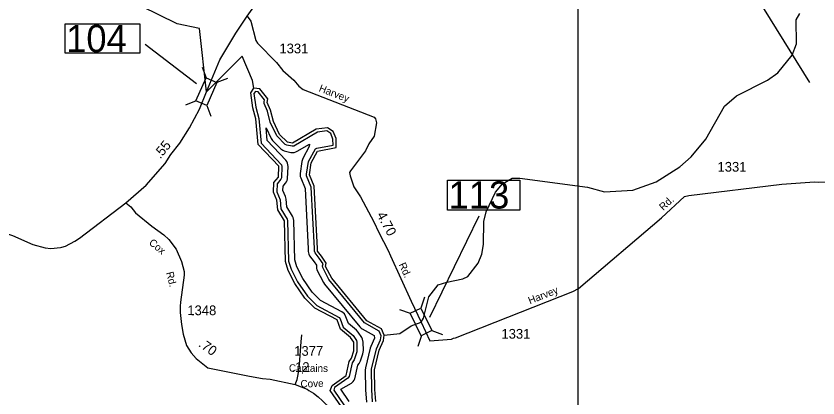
# Model space of a CAD drawing. Extents: x 2532689 to 2764727, y 536648 to 732970.
# Drawn here: x 2602829 to 2613131, y 643101 to 648009 of the extents above; entities that cross this region are included whole.
import ezdxf

# ---------------------------------------------------------------- set-up
doc = ezdxf.new("R2010")
doc.units = 0
for name, color, linetype in [('Exist Hydrographic Buffer Line', 7, 'Continuous'), ('Exist Hydrographic Creek Single Shore', 7, 'Continuous'), ('Exist Hydrographic River Shore', 7, 'Continuous'), ('Exist Road Primary NC Attributed', 7, 'Continuous'), ('Exist Road Primary NC Mileage Hundredths English Label', 7, 'Continuous'), ('Exist Road Primary NC Structure Standard Bridge CELL', 7, 'Continuous'), ('Exist Road Primary NC Structure Standard Bridge Number Label', 7, 'Continuous'), ('Exist Road Secondary Mileage Hundredths English Label', 7, 'Continuous'), ('Exist Road Secondary Structure Standard Bridge CELL', 7, 'Continuous'), ('Exist Road Secondary Structure Standard Bridge Number Label', 7, 'Continuous'), ('Exist Road Secondary Type 51 Attributed', 7, 'Continuous'), ('Exist Road Secondary Type 51 Label', 7, 'Continuous'), ('Exist Road Secondary Type 51 Number Label', 7, 'Continuous'), ('Map Preparation Inset Cut Line', 7, 'Continuous')]:
    doc.layers.add(name, color=color, linetype=linetype)

msp = doc.modelspace()

# ---------------------------------------------------------------- linework, layer by layer
at = {"layer": 'Exist Hydrographic Buffer Line'}
for points in [[(2607410, 643053), (2607400, 643208), (2607396, 643472), (2607460, 643731), (2607513, 643849), (2607518, 643901), (2607493, 643960), (2607307, 644066), (2606849, 644623), (2606770, 644776), (2606768, 644797), (2606773, 644824), (2606723, 644899), (2606672, 644964), (2606663, 644988), (2606662, 645020), (2606621, 645812), (2606562, 645954), (2606560, 645975), (2606586, 646140), (2606675, 646303), (2606693, 646312), (2606902, 646351), (2606900, 646428), (2606872, 646500), (2606820, 646532), (2606700, 646516), (2606397, 646337), (2606375, 646335), (2606308, 646349), (2606288, 646359), (2606178, 646469), (2606096, 646644), (2606061, 646787), (2606018, 646886), (2606016, 646906), (2606020, 646932), (2605939, 647035), (2605904, 647038), (2605886, 647012), (2605912, 646838), (2605949, 646694), (2605979, 646374), (2606240, 646098), (2606245, 646077), (2606239, 645930), (2606231, 645911), (2606182, 645854), (2606178, 645752), (2606221, 645648), (2606231, 645533), (2606312, 645400), (2606318, 645380), (2606329, 644861), (2606362, 644756), (2606446, 644594), (2606572, 644410), (2606692, 644288), (2606981, 644133), (2606993, 644117), (2607033, 644010), (2607159, 643902), (2607202, 643838), (2607209, 643817), (2607209, 643695), (2607172, 643591), (2607146, 643554), (2607108, 643375), (2607093, 643356), (2606922, 643234), (2606910, 643202), (2607049, 642999)], [(2606304, 645877), (2606313, 645896), (2606318, 645916), (2606325, 646074), (2606323, 646099), (2606318, 646120), (2606309, 646138), (2606297, 646156), (2606057, 646409), (2606041, 646572), (2606106, 646435), (2606122, 646409), (2606233, 646302), (2606256, 646284), (2606275, 646275), (2606359, 646257), (2606383, 646255), (2606404, 646256), (2606424, 646262), (2606443, 646271), (2606601, 646364), (2606597, 646333), (2606515, 646178), (2606502, 646139), (2606480, 645987), (2606481, 645949), (2606486, 645929), (2606542, 645794), (2606582, 645017), (2606583, 644985), (2606590, 644948), (2606599, 644929), (2606658, 644852), (2606689, 644806), (2606689, 644769), (2606694, 644748), (2606779, 644586), (2606792, 644565), (2607246, 644016), (2607261, 644000), (2607278, 643988), (2607430, 643903), (2607434, 643870), (2607387, 643764), (2607379, 643743), (2607318, 643490), (2607315, 643460), (2607320, 643206), (2607330, 643048)], [(2607109, 643057), (2607000, 643213), (2607140, 643291), (2607162, 643311), (2607174, 643328), (2607183, 643347), (2607220, 643521), (2607237, 643544), (2607254, 643577), (2607285, 643670), (2607291, 643710), (2607289, 643818), (2607282, 643857), (2607273, 643876), (2607226, 643947), (2607203, 643972), (2607100, 644058), (2607067, 644145), (2607047, 644180), (2607032, 644195), (2607015, 644207), (2606741, 644353), (2606634, 644461), (2606515, 644635), (2606436, 644787), (2606409, 644874), (2606398, 645381), (2606391, 645420), (2606382, 645439), (2606309, 645558), (2606301, 645655), (2606291, 645692), (2606258, 645767), (2606261, 645823), (2606292, 645860), (2606304, 645877)]]:
    msp.add_lwpolyline(points, dxfattribs=at)
at = {"layer": 'Exist Hydrographic Creek Single Shore'}
for points in [[(2605885, 647080), (2605866, 647181), (2605734, 647494), (2605275, 647033), (2605185, 647849), (2604901, 647910), (2604437, 648134), (2604277, 648256), (2604159, 648320)], [(2607559, 643907), (2607759, 643928), (2607906, 644030), (2608032, 644076), (2608063, 644125), (2608132, 644400), (2608254, 644553), (2608362, 644590), (2608569, 644634), (2608635, 644663), (2608765, 644833), (2608812, 644949), (2608835, 645075), (2608837, 645367), (2608868, 645493), (2608988, 645744), (2609077, 645853), (2609201, 645924), (2609301, 645925), (2610170, 645812), (2610388, 645749), (2610754, 645773), (2611052, 645880), (2611356, 646070), (2611504, 646198), (2611691, 646425), (2611932, 646849), (2612087, 646983), (2612483, 647183), (2612614, 647280), (2612801, 647508), (2612857, 647651), (2612850, 647959), (2612899, 648043)]]:
    msp.add_lwpolyline(points, dxfattribs=at)
at = {"layer": 'Exist Hydrographic River Shore'}
for points in [[(2606865, 643197), (2606889, 643260), (2607070, 643388), (2607108, 643570), (2607140, 643614), (2607171, 643708), (2607169, 643816), (2607126, 643880), (2606999, 643986), (2606955, 644103), (2606668, 644255), (2606541, 644385), (2606412, 644573), (2606325, 644740), (2606289, 644854), (2606278, 645379), (2606192, 645520), (2606181, 645644), (2606137, 645744), (2606143, 645869), (2606200, 645937), (2606205, 646078), (2605941, 646357), (2605909, 646690), (2605873, 646830), (2605844, 647023), (2605885, 647080)], [(2607559, 643907), (2607524, 643988), (2607338, 644092), (2606885, 644642), (2606807, 644790), (2606815, 644833), (2606755, 644922), (2606703, 644989), (2606702, 645022), (2606661, 645821), (2606599, 645970), (2606621, 646122), (2606701, 646273), (2606942, 646318), (2606940, 646436), (2606904, 646527), (2606829, 646573), (2606687, 646554), (2606383, 646375), (2606316, 646388), (2606214, 646486), (2606135, 646653), (2606099, 646800), (2606055, 646900), (2606062, 646943), (2605960, 647073), (2605885, 647080)], [(2607440, 643209), (2607435, 643462), (2607496, 643714), (2607552, 643838), (2607559, 643907)], [(2607010, 642989), (2606865, 643197)], [(2607450, 643056), (2607440, 643209)]]:
    msp.add_lwpolyline(points, dxfattribs=at)
at = {"layer": 'Exist Road Primary NC Attributed'}
msp.add_line((2605798, 648006), (2606528, 649048), dxfattribs=at)
for points in [[(2605275, 647033), (2605447, 647448), (2605652, 647791), (2605798, 648006)], [(2604241, 645609), (2604499, 645835), (2604745, 646115), (2604816, 646230), (2604934, 646375), (2605057, 646574), (2605187, 646812), (2605275, 647033)], [(2600881, 644849), (2601610, 645177), (2601850, 645266), (2602055, 645314), (2602293, 645313), (2602407, 645295), (2602520, 645276), (2602782, 645189), (2603044, 645073), (2603205, 645030), (2603277, 645022), (2603401, 645036), (2603417, 645038), (2603466, 645051), (2603585, 645114), (2603646, 645155), (2604241, 645609)]]:
    msp.add_lwpolyline(points, dxfattribs=at)
at = {"layer": 'Exist Road Primary NC Structure Standard Bridge CELL'}
for p, q in [((2605219, 647351), (2605272, 647214)), ((2605547, 647206), (2605409, 647153)), ((2605144, 646918), (2605007, 646865)), ((2605279, 646859), (2605332, 646722))]:
    msp.add_line(p, q, dxfattribs=at)
msp.add_lwpolyline([(2605409, 647153), (2605279, 646859), (2605141, 646919), (2605272, 647214)], close=True, dxfattribs=at)
at = {"layer": 'Exist Road Primary NC Structure Standard Bridge Number Label'}
msp.add_line((2605147, 647136), (2604487, 647645), dxfattribs=at)
msp.add_lwpolyline([(2603460, 647908), (2604421, 647908), (2604421, 647533), (2603460, 647533)], close=True, dxfattribs=at)
at = {"layer": 'Exist Road Secondary Structure Standard Bridge CELL'}
for p, q in [((2608078, 644395), (2608030, 644256)), ((2607755, 644239), (2607894, 644191)), ((2608037, 643902), (2607989, 643763)), ((2608170, 643966), (2608309, 643918))]:
    msp.add_line(p, q, dxfattribs=at)
msp.add_lwpolyline([(2608030, 644256), (2608171, 643967), (2608035, 643901), (2607894, 644191)], close=True, dxfattribs=at)
at = {"layer": 'Exist Road Secondary Structure Standard Bridge Number Label'}
msp.add_line((2608146, 644141), (2608777, 645440), dxfattribs=at)
msp.add_lwpolyline([(2608372, 645900), (2609301, 645900), (2609301, 645516), (2608372, 645516)], close=True, dxfattribs=at)
at = {"layer": 'Exist Road Secondary Type 51 Attributed'}
for points in [[(2605798, 648006), (2605845, 647941), (2605912, 647693), (2605933, 647661), (2606174, 647410), (2606258, 647308), (2606396, 647185), (2606464, 647108), (2606519, 647067), (2607432, 646710), (2607449, 646689), (2607460, 646637), (2607432, 646466), (2607362, 646365), (2607320, 646278), (2607125, 646019), (2607115, 645999), (2607120, 645956), (2607169, 645814), (2607254, 645684), (2607427, 645364), (2607488, 645229), (2607610, 644998), (2607638, 644926), (2607906, 644344), (2608032, 644076)], [(2608032, 644076), (2608146, 643837), (2608422, 643856), (2608450, 643871), (2608474, 643875), (2609982, 644467), (2610055, 644508), (2611120, 645414), (2611418, 645689), (2611474, 645704), (2612669, 645847), (2613089, 645878), (2613133, 645874), (2613780, 645898), (2613866, 645922), (2614880, 646511), (2615971, 646942), (2616071, 646960), (2616289, 646996), (2616610, 646989), (2616662, 646986), (2616790, 646985)], [(2604241, 645609), (2604304, 645557), (2604366, 645480), (2604575, 645309), (2604726, 645198), (2604791, 645139), (2604885, 645011), (2604957, 644854), (2604990, 644727), (2604990, 644681), (2604940, 644330), (2604937, 644282), (2604936, 644198), (2604956, 644046), (2604978, 643919), (2605019, 643777), (2605081, 643679), (2605145, 643608), (2605295, 643487), (2605828, 643380), (2605994, 643353), (2606092, 643341), (2606417, 643273)], [(2606417, 643273), (2606439, 643337), (2606454, 643402), (2606471, 643532), (2606491, 643823), (2606501, 643911)], [(2606417, 643273), (2606569, 643213), (2606591, 643195), (2606649, 643161), (2606711, 643116), (2606766, 643066), (2606824, 643007), (2606935, 642851), (2607004, 642729), (2607055, 642617), (2607079, 642533), (2607101, 642416), (2607109, 642333), (2607097, 642165), (2607057, 641988), (2607026, 641891), (2606970, 641788), (2606921, 641723), (2606848, 641655), (2606749, 641579), (2606638, 641521), (2606567, 641491), (2606407, 641440)]]:
    msp.add_lwpolyline(points, dxfattribs=at)
at = {"layer": 'Exist Road Secondary Type 51 Number Label'}
msp.add_lwpolyline([(2611349, 651205), (2611221, 649486), (2612011, 648789), (2613024, 647157)], dxfattribs=at)
at = {"layer": 'Map Preparation Inset Cut Line'}
msp.add_lwpolyline([(2549571, 680600), (2610045, 680600), (2610045, 636352), (2549571, 636352)], close=True, dxfattribs=at)

# ---------------------------------------------------------------- texts
at = {"layer": 'Exist Road Primary NC Mileage Hundredths English Label'}
msp.add_text('.55', height=125, rotation=51.0433, dxfattribs=at).set_placement((2604683, 646165))
at = {"layer": 'Exist Road Primary NC Structure Standard Bridge Number Label'}
msp.add_text('104', height=350, dxfattribs=at).set_placement((2603472, 647545))
at = {"layer": 'Exist Road Secondary Mileage Hundredths English Label'}
for s, rotation, p in [('4.70', 298.2453, (2607459, 645455)), ('.70', 324.27, (2605164, 643771)), ('.12', 359.8507, (2606367, 643436))]:
    msp.add_text(s, height=125, rotation=rotation, dxfattribs=at).set_placement(p)
at = {"layer": 'Exist Road Secondary Structure Standard Bridge Number Label'}
msp.add_text('113', height=350, dxfattribs=at).set_placement((2608385, 645535))
at = {"layer": 'Exist Road Secondary Type 51 Label'}
for s, rotation, p in [('Harvey', 338.6506, (2606712, 647045)), ('Rd.', 42.6208, (2611144, 645503)), ('Cox', 320.7069, (2604528, 645082)), ('Rd.', 294.7229, (2607743, 644815)), ('Rd.', 284.4117, (2604756, 644711)), ('Harvey', 21.4191, (2609431, 644304)), ('Captains', 359.5493, (2606335, 643439)), ('Cove', 1.655, (2606485, 643235))]:
    msp.add_text(s, height=95, rotation=rotation, dxfattribs=at).set_placement(p)
at = {"layer": 'Exist Road Secondary Type 51 Number Label'}
for s, p in [('1331', (2606213, 647530)), ('1348', (2605030, 644165)), ('1331', (2609065, 643863)), ('1377', (2606403, 643643))]:
    msp.add_text(s, height=125, rotation=359.94, dxfattribs=at).set_placement(p)
msp.add_text('1331', height=125, dxfattribs=at).set_placement((2611841, 646009))

doc.saveas('drawing.dxf')
